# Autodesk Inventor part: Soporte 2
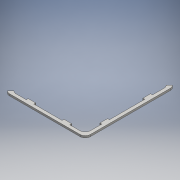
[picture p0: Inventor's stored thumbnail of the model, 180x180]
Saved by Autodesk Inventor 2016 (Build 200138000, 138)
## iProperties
Created: 2016-06
Part Number: Soporte 2
Material: Genérico
Document SubType Name: Modeling
Designer: adm
Density: 1 g/cm^3
Appearance: Valor por defecto
Author: adm
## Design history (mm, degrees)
sketch "Boceto1"
  geometry: L1 (3, 0)-(113, 0); L2 (121, 8)-(121, 133); L3 (116, 110)-(113, 110); L4 (113, 110)-(113, 98); L5 (113, 98)-(116, 98); L6 (116, 43)-(113, 43); L7 (113, 43)-(113, 31); L8 (113, 31)-(116, 31); L9 (36, 5)-(36, 8); L10 (36, 8)-(24, 8); L11 (24, 8)-(24, 5); L12 (92, 5)-(92, 8); L13 (92, 8)-(80, 8); L14 (80, 8)-(80, 5); L15 (108, 5)-(92, 5); L16 (80, 5)-(36, 5); L17 (24, 5)-(8, 5); L18 (116, 31)-(116, 13); L19 (116, 128)-(116, 110); L20 (116, 98)-(116, 43); L21 (121, 136)-(131, 136); L22 (-5, 5.005)-(-5, 5); L23 (-2.657, 2.343)-(2.343, 7.343); L24 (118.657, 138.657)-(113.657, 133.657); L25 (121, 141)-(131, 141); L26 (58, -7)-(58, -12.346); L27 (149, 70.5)-(183, 70.5); A1 r 8 centre (108, 13) between (108, 5) and (116, 13); A2 r 8 centre (113, 8) between (113, 0) and (121, 8); A3 r 8 centre (108, 128) between (116, 128) and (113.657, 133.657); A4 r 8 centre (113, 133) between (121, 133) and (118.657, 138.657); A5 r 8 centre (8, 13) between (2.343, 7.343) and (8, 5); A6 r 8 centre (3, 8) between (-2.657, 2.343) and (3, 0); 23 further points
  constraints: 54 end point, 19 symmetric about line, 15 point on line, 12 perpendicular, 12 point on circle, 6 centre point, 6 horizontal, 4 parallel, 4 tangent, 2 vertical, 1 equal radius, 4 other
  dimensions: "d7" = 12 distance of L3.end L4.end; "d11" = 12 distance of L6.end L7.end; "d12" = 55 distance between parallel lines of L6 L5; "d13" = 3 distance of L7.end L8.end; "d15" = 12 distance of L9.end L10.end; "d16" = 3 distance of L9.start L9.end; "d17" = 12 distance of L12.end L13.end; "d18" = 3 distance of L12.start L12.end; "d19" = 44 distance between parallel lines of L14 L9; "d30" = 5 distance of L21.start L25.start; "d32" = 135 deg angle of L24 L25; "d34" = 70.5 distance between parallel lines of L1 L27; "d35" = 8 radius of A1
extrude "Extrusión1" new body sketch "Boceto1" distance "d20" = 3; taper "d21" = 0 deg
node "Sólido1"
other parameters: "d0" = 116, "d1" = 5, "d2" = 5
